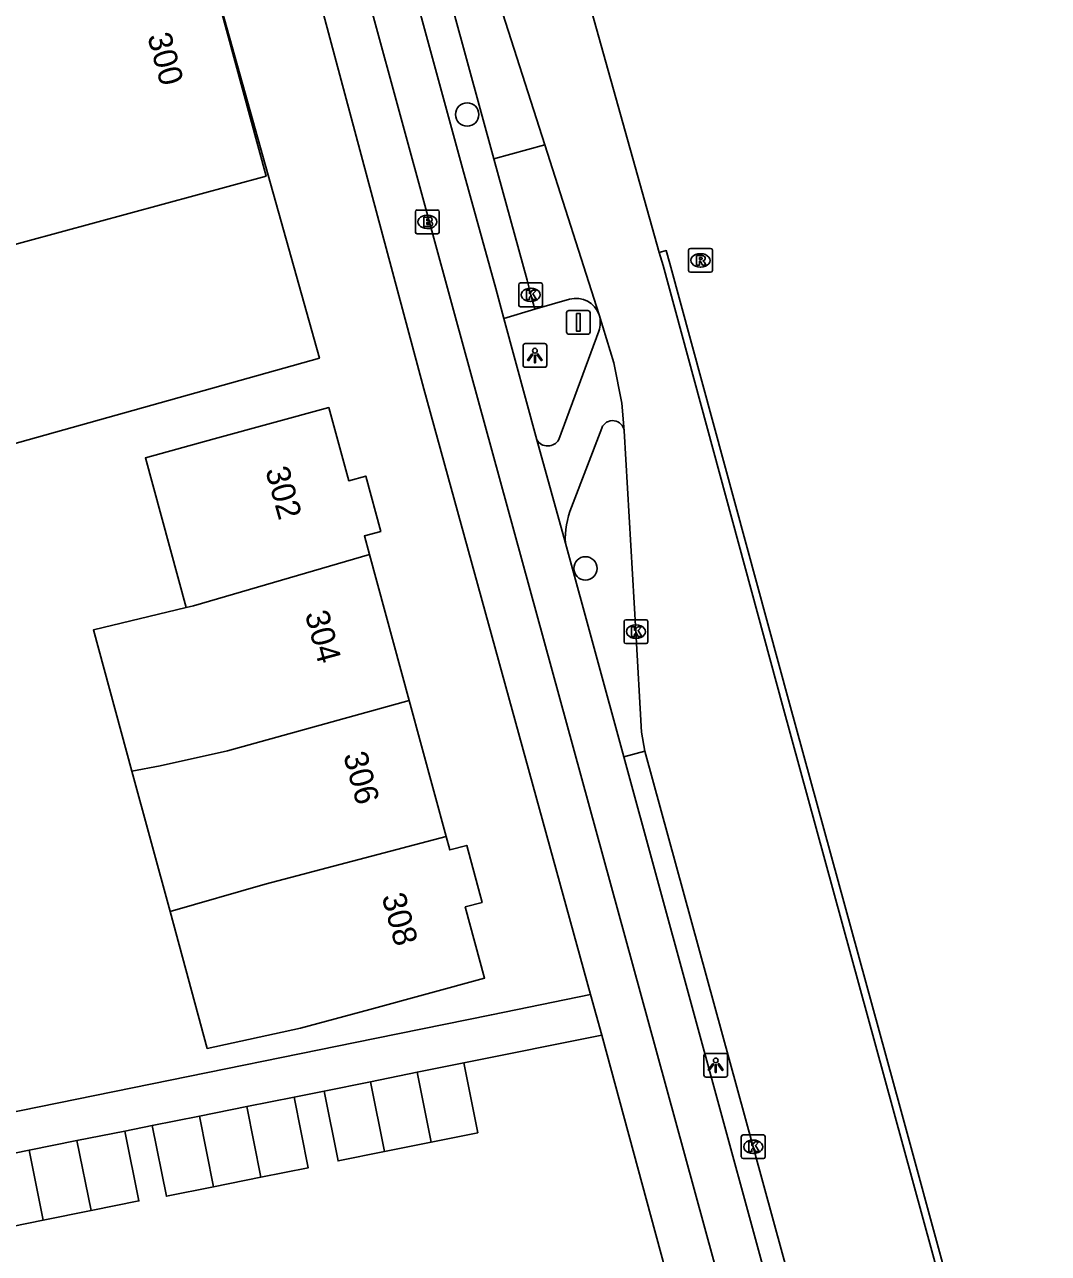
# Model space of a CAD drawing. Extents: x 162250 to 162654, y 380744 to 381605.
# Drawn here: x 162593.3 to 162636.4, y 380879.3 to 380930.9 of the extents above; entities that cross this region are included whole.
import ezdxf

# ---------------------------------------------------------------- set-up
doc = ezdxf.new("R2010")
doc.units = 0
for name, color, linetype in [('IMGEO_Boom', 7, 'Continuous'), ('IMGEO_Brandkraan', 7, 'Continuous'), ('IMGEO_Fietspad_gesloten', 7, 'Continuous'), ('IMGEO_Fietspad_open', 7, 'Continuous'), ('IMGEO_Kolk', 7, 'Continuous'), ('IMGEO_Lichtpunt', 7, 'Continuous'), ('IMGEO_Pand', 7, 'Continuous'), ('IMGEO_Pand_nummerreeks', 7, 'Continuous'), ('IMGEO_Pand_vergunning_verleend', 7, 'Continuous'), ('IMGEO_Parkeervlak_open', 7, 'Continuous'), ('IMGEO_Rijbaan_regionaal_gesloten', 7, 'Continuous'), ('IMGEO_Rioolput', 7, 'Continuous'), ('IMGEO_Verkeersbordpaal', 7, 'Continuous'), ('IMGEO_Verkeerseiland_groen', 7, 'Continuous'), ('IMGEO_Voetpad_open', 7, 'Continuous')]:
    doc.layers.add(name, color=color, linetype=linetype)

msp = doc.modelspace()

# ---------------------------------------------------------------- linework, layer by layer
at = {"layer": 'IMGEO_Boom'}
for centre in [(162611.944, 380927.149), (162616.915, 380908.077)]:
    msp.add_circle(centre, 0.489, dxfattribs=at)
at = {"layer": 'IMGEO_Brandkraan'}
for p, q in [((162609.77, 380922.21), (162609.77, 380923.062)), ((162609.845, 380923.136), (162610.697, 380923.136)), ((162610.258, 380922.916), (162610.283, 380922.916)), ((162610.771, 380923.062), (162610.771, 380922.21)), ((162610.281, 380922.356), (162610.256, 380922.356)), ((162610.697, 380922.136), (162609.845, 380922.136))]:
    msp.add_line(p, q, dxfattribs=at)
for points in [[(162609.77, 380922.21), (162609.77, 380923.062)], [(162609.845, 380923.136), (162610.697, 380923.136)], [(162610.771, 380923.062), (162610.771, 380922.21)], [(162610.118, 380922.836), (162610.118, 380922.436), (162610.331, 380922.436)], [(162610.349, 380922.836), (162610.118, 380922.836)], [(162610.297, 380922.755), (162610.243, 380922.755), (162610.243, 380922.679)], [(162610.243, 380922.679), (162610.296, 380922.679)], [(162610.305, 380922.603), (162610.243, 380922.603), (162610.243, 380922.522)], [(162610.243, 380922.522), (162610.305, 380922.522)], [(162610.697, 380922.136), (162609.845, 380922.136)]]:
    msp.add_lwpolyline(points, dxfattribs=at)
for centre, radius, start, end in [((162609.847, 380923.06), 0.0765, 91.552, 178.448), ((162609.847, 380923.06), 0.0765, 91.552, 178.448), ((162610.695, 380923.06), 0.0765, 1.552, 88.448), ((162610.695, 380923.06), 0.0765, 1.552, 88.448), ((162610.298, 380922.717), 0.0379, 267.8285, 90.9355), ((162610.306, 380922.562), 0.0404, 269.8759, 90.5077), ((162610.337, 380922.687), 0.251, 268.6676, 293.5347), ((162610.353, 380922.691), 0.145, 59.4692, 91.5367), ((162610.378, 380922.738), 0.0922, 285.5137, 58.1501), ((162610.383, 380922.546), 0.105, 301.3115, 78.989), ((162609.847, 380922.212), 0.0765, 181.552, 268.448), ((162609.847, 380922.212), 0.0765, 181.552, 268.448), ((162610.695, 380922.212), 0.0765, 271.552, 358.448), ((162610.695, 380922.212), 0.0765, 271.552, 358.448)]:
    msp.add_arc(centre, radius, start, end, dxfattribs=at)
for centre, major_axis, ratio, start_param, end_param in [((162610.257, 380922.636), (-0.387, 0.002), 0.722429, 4.712389, 7.853982), ((162610.282, 380922.636), (-0.39, 0.002), 0.717154, 1.570796, 4.712389)]:
    msp.add_ellipse(centre, major_axis=major_axis, ratio=ratio, start_param=start_param, end_param=end_param, dxfattribs=at)
at = {"layer": 'IMGEO_Fietspad_gesloten'}
for points in [[(162536.398, 381200.372), (162539.144, 381190.342), (162540.943, 381183.77), (162548.984, 381154.395), (162551.592, 381144.84), (162551.645, 381144.647), (162554.806, 381133.124), (162560.736, 381111.446), (162562.992, 381103.198), (162573.052, 381066.398), (162577.335, 381050.801), (162584.526, 381024.553), (162587.309, 381014.367), (162588.433, 381010.254), (162590.219, 381003.716), (162603.154, 380956.316), (162606.977, 380942.372), (162608.338, 380937.386), (162611.747, 380924.889), (162613.149, 380919.833), (162613.482, 380918.571)], [(162626.231, 380864.638), (162619.54, 380889.111), (162611.456, 380918.623), (162600.985, 380956.955), (162588.336, 381003.241), (162586.64, 381009.407), (162585.413, 381013.87), (162582.804, 381023.355), (162575.392, 381050.363), (162571.085, 381066.091), (162561.27, 381101.934), (162558.72, 381111.249), (162552.836, 381132.744), (162549.852, 381143.643)], [(162614.869, 380913.477), (162613.482, 380918.571)], [(162616.074, 380909.136), (162614.869, 380913.477)], [(162618.527, 380900.159), (162616.074, 380909.136)], [(162628.093, 380865.109), (162618.527, 380900.159)]]:
    msp.add_lwpolyline(points, dxfattribs=at)
at = {"layer": 'IMGEO_Fietspad_open'}
for points in [[(162615.795, 380913.486), (162617.477, 380918.04)], [(162617.598, 380913.973), (162616.334, 380910.645)]]:
    msp.add_lwpolyline(points, dxfattribs=at)
for centre, radius, start, end in [((162616.332, 380918.413), 1.204, 341.9353, 15.242), ((162618.057, 380913.795), 0.492, 6.7574, 158.799), ((162615.329, 380913.763), 0.542, 211.8287, 329.285), ((162619.429, 380909.335), 3.361, 157.0559, 183.392)]:
    msp.add_arc(centre, radius, start, end, dxfattribs=at)
at = {"layer": 'IMGEO_Kolk'}
for p, q in [((162614.113, 380919.144), (162614.113, 380919.996)), ((162614.188, 380920.07), (162615.04, 380920.07)), ((162614.601, 380919.85), (162614.626, 380919.85)), ((162615.114, 380919.996), (162615.114, 380919.144)), ((162614.624, 380919.29), (162614.599, 380919.29)), ((162615.04, 380919.07), (162614.188, 380919.07)), ((162618.535, 380904.994), (162618.535, 380905.846)), ((162618.61, 380905.92), (162619.462, 380905.92)), ((162619.536, 380905.846), (162619.536, 380904.994)), ((162619.023, 380905.7), (162619.048, 380905.7)), ((162619.462, 380904.92), (162618.61, 380904.92)), ((162619.046, 380905.14), (162619.021, 380905.14)), ((162623.464, 380883.349), (162623.464, 380884.201)), ((162623.539, 380884.275), (162624.391, 380884.275)), ((162624.465, 380884.201), (162624.465, 380883.349)), ((162623.952, 380884.055), (162623.977, 380884.055)), ((162624.391, 380883.275), (162623.539, 380883.275)), ((162623.975, 380883.495), (162623.95, 380883.495))]:
    msp.add_line(p, q, dxfattribs=at)
for points in [[(162614.113, 380919.144), (162614.113, 380919.996)], [(162614.188, 380920.07), (162615.04, 380920.07)], [(162614.434, 380919.77), (162614.557, 380919.77), (162614.557, 380919.619), (162614.687, 380919.77), (162614.851, 380919.77), (162614.705, 380919.619), (162614.858, 380919.37), (162614.706, 380919.37), (162614.621, 380919.534), (162614.557, 380919.467), (162614.557, 380919.37), (162614.434, 380919.37), (162614.434, 380919.77)], [(162615.114, 380919.996), (162615.114, 380919.144)], [(162615.04, 380919.07), (162614.188, 380919.07)], [(162618.535, 380904.994), (162618.535, 380905.846)], [(162618.61, 380905.92), (162619.462, 380905.92)], [(162619.536, 380905.846), (162619.536, 380904.994)], [(162618.856, 380905.62), (162618.979, 380905.62), (162618.979, 380905.469), (162619.109, 380905.62), (162619.273, 380905.62), (162619.127, 380905.469), (162619.28, 380905.22), (162619.128, 380905.22), (162619.043, 380905.384), (162618.979, 380905.317), (162618.979, 380905.22), (162618.856, 380905.22), (162618.856, 380905.62)], [(162619.462, 380904.92), (162618.61, 380904.92)], [(162623.464, 380883.349), (162623.464, 380884.201)], [(162623.539, 380884.275), (162624.391, 380884.275)], [(162624.465, 380884.201), (162624.465, 380883.349)], [(162623.785, 380883.975), (162623.908, 380883.975), (162623.908, 380883.824), (162624.038, 380883.975), (162624.202, 380883.975), (162624.056, 380883.824), (162624.209, 380883.575), (162624.057, 380883.575), (162623.972, 380883.739), (162623.908, 380883.672), (162623.908, 380883.575), (162623.785, 380883.575), (162623.785, 380883.975)], [(162624.391, 380883.275), (162623.539, 380883.275)]]:
    msp.add_lwpolyline(points, dxfattribs=at)
for centre, start, end in [((162614.19, 380919.994), 91.552, 178.448), ((162614.19, 380919.994), 91.552, 178.448), ((162615.038, 380919.994), 1.552, 88.448), ((162615.038, 380919.994), 1.552, 88.448), ((162614.19, 380919.146), 181.552, 268.448), ((162614.19, 380919.146), 181.552, 268.448), ((162615.038, 380919.146), 271.552, 358.448), ((162615.038, 380919.146), 271.552, 358.448), ((162618.612, 380905.844), 91.552, 178.448), ((162618.612, 380905.844), 91.552, 178.448), ((162619.46, 380905.844), 1.552, 88.448), ((162619.46, 380905.844), 1.552, 88.448), ((162618.612, 380904.996), 181.552, 268.448), ((162618.612, 380904.996), 181.552, 268.448), ((162619.46, 380904.996), 271.552, 358.448), ((162619.46, 380904.996), 271.552, 358.448), ((162623.541, 380884.199), 91.552, 178.448), ((162623.541, 380884.199), 91.552, 178.448), ((162624.389, 380884.199), 1.552, 88.448), ((162624.389, 380884.199), 1.552, 88.448), ((162623.541, 380883.351), 181.552, 268.448), ((162623.541, 380883.351), 181.552, 268.448), ((162624.389, 380883.351), 271.552, 358.448), ((162624.389, 380883.351), 271.552, 358.448)]:
    msp.add_arc(centre, 0.0765, start, end, dxfattribs=at)
for centre, major_axis, ratio, start_param, end_param in [((162614.6, 380919.57), (-0.387, 0.002), 0.722429, 4.712389, 7.853982), ((162614.625, 380919.57), (-0.39, 0.002), 0.717154, 1.570796, 4.712389), ((162619.022, 380905.42), (-0.387, 0.002), 0.722429, 4.712389, 7.853982), ((162619.047, 380905.42), (-0.39, 0.002), 0.717154, 1.570796, 4.712389), ((162623.951, 380883.775), (-0.387, 0.002), 0.722429, 4.712389, 7.853982), ((162623.976, 380883.775), (-0.39, 0.002), 0.717154, 1.570796, 4.712389)]:
    msp.add_ellipse(centre, major_axis=major_axis, ratio=ratio, start_param=start_param, end_param=end_param, dxfattribs=at)
at = {"layer": 'IMGEO_Lichtpunt'}
for p, q in [((162614.291, 380917.427), (162614.291, 380916.62)), ((162614.291, 380917.427), (162614.291, 380916.62)), ((162615.193, 380917.522), (162614.385, 380917.522)), ((162615.193, 380917.522), (162614.385, 380917.522)), ((162615.287, 380916.62), (162615.287, 380917.427)), ((162615.287, 380916.62), (162615.287, 380917.427)), ((162614.385, 380916.526), (162615.193, 380916.526)), ((162614.385, 380916.526), (162615.193, 380916.526)), ((162621.889, 380887.604), (162621.889, 380886.797)), ((162621.889, 380887.604), (162621.889, 380886.797)), ((162622.791, 380887.699), (162621.983, 380887.699)), ((162622.791, 380887.699), (162621.983, 380887.699)), ((162622.885, 380886.797), (162622.885, 380887.604)), ((162622.885, 380886.797), (162622.885, 380887.604)), ((162621.983, 380886.703), (162622.791, 380886.703)), ((162621.983, 380886.703), (162622.791, 380886.703))]:
    msp.add_line(p, q, dxfattribs=at)
for points in [[(162614.665, 380917.091), (162614.704, 380917.063), (162614.516, 380916.801), (162614.478, 380916.828), (162614.665, 380917.091)], [(162614.767, 380917.043), (162614.814, 380917.043), (162614.814, 380916.721), (162614.767, 380916.721), (162614.767, 380917.043)], [(162614.877, 380917.063), (162614.915, 380917.09), (162615.102, 380916.828), (162615.063, 380916.8), (162614.877, 380917.063)], [(162622.263, 380887.268), (162622.302, 380887.24), (162622.114, 380886.978), (162622.076, 380887.005), (162622.263, 380887.268)], [(162622.365, 380887.22), (162622.412, 380887.22), (162622.412, 380886.898), (162622.365, 380886.898), (162622.365, 380887.22)], [(162622.475, 380887.24), (162622.513, 380887.267), (162622.7, 380887.005), (162622.661, 380886.977), (162622.475, 380887.24)]]:
    msp.add_lwpolyline(points, dxfattribs=at)
for centre in [(162614.79, 380917.225), (162622.388, 380887.402)]:
    msp.add_circle(centre, 0.0994, dxfattribs=at)
for centre, start, end in [((162614.385, 380917.427), 90, 180), ((162614.385, 380917.427), 90, 180), ((162615.193, 380917.427), 0, 90), ((162615.193, 380917.427), 0, 90), ((162614.385, 380916.62), 180, 270), ((162614.385, 380916.62), 180, 270), ((162615.193, 380916.62), 270, 0), ((162615.193, 380916.62), 270, 360), ((162621.983, 380887.604), 90, 180), ((162621.983, 380887.604), 90, 180), ((162622.791, 380887.604), 0, 90), ((162622.791, 380887.604), 0, 90), ((162621.983, 380886.797), 180, 270), ((162621.983, 380886.797), 180, 270), ((162622.791, 380886.797), 270, 0), ((162622.791, 380886.797), 270, 360)]:
    msp.add_arc(centre, 0.0946, start, end, dxfattribs=at)
at = {"layer": 'IMGEO_Pand'}
for points in [[(162599.77, 380935.183), (162600.55, 380935.395), (162603.496, 380924.559), (162581.842, 380918.674), (162582.635, 380915.76), (162577.91, 380914.476)], [(162607.84, 380908.665), (162607.628, 380909.443), (162608.316, 380909.63), (162607.684, 380911.953), (162606.968, 380911.758), (162606.131, 380914.837), (162601.307, 380913.526), (162598.427, 380912.717), (162600.136, 380906.429)], [(162607.84, 380908.665), (162600.448, 380906.503), (162600.136, 380906.429)], [(162609.509, 380902.523), (162607.84, 380908.665)], [(162600.136, 380906.429), (162596.238, 380905.5), (162597.853, 380899.561)], [(162597.853, 380899.561), (162599.042, 380899.777), (162601.877, 380900.417), (162609.509, 380902.523)], [(162609.509, 380902.523), (162611.062, 380896.809)], [(162599.458, 380893.661), (162597.853, 380899.561)], [(162611.062, 380896.809), (162611.215, 380896.246), (162611.923, 380896.438), (162612.573, 380894.044), (162611.863, 380893.851), (162612.676, 380890.86), (162607.852, 380889.548), (162604.939, 380888.756), (162601.023, 380887.907), (162599.458, 380893.661)], [(162599.458, 380893.661), (162603.459, 380894.815), (162611.062, 380896.809)], [(162611.801, 380887.295), (162609.844, 380886.902)], [(162610.433, 380883.968), (162612.39, 380884.361), (162611.801, 380887.295)], [(162609.844, 380886.902), (162607.887, 380886.509)], [(162609.844, 380886.902), (162610.433, 380883.968)], [(162607.887, 380886.509), (162605.93, 380886.116)], [(162608.476, 380883.575), (162607.887, 380886.509)], [(162604.67, 380885.863), (162602.682, 380885.464)], [(162603.279, 380882.492), (162605.266, 380882.891), (162604.67, 380885.863)], [(162605.93, 380886.116), (162606.52, 380883.182), (162608.476, 380883.575)], [(162602.682, 380885.464), (162600.694, 380885.064)], [(162603.279, 380882.492), (162602.682, 380885.464)], [(162600.694, 380885.064), (162598.707, 380884.665)], [(162598.707, 380884.665), (162599.304, 380881.694), (162601.291, 380882.093)], [(162601.291, 380882.093), (162600.694, 380885.064)], [(162597.559, 380884.435), (162595.548, 380884.031)], [(162596.138, 380881.092), (162598.149, 380881.496), (162597.559, 380884.435)], [(162593.541, 380883.628), (162591.533, 380883.225)], [(162595.548, 380884.031), (162593.541, 380883.628)], [(162594.131, 380880.689), (162593.541, 380883.628)], [(162596.138, 380881.092), (162595.548, 380884.031)], [(162608.476, 380883.575), (162610.433, 380883.968)], [(162591.533, 380883.225), (162592.124, 380880.286), (162594.131, 380880.689)], [(162601.291, 380882.093), (162603.279, 380882.492)], [(162594.131, 380880.689), (162596.138, 380881.092)]]:
    msp.add_lwpolyline(points, dxfattribs=at)
at = {"layer": 'IMGEO_Pand_vergunning_verleend'}
msp.add_lwpolyline([(162586.803, 380931.515), (162593.538, 380933.518), (162599.77, 380935.183), (162600.55, 380935.395), (162605.736, 380916.916), (162591.983, 380913.056), (162586.803, 380931.515)], dxfattribs=at)
at = {"layer": 'IMGEO_Parkeervlak_open'}
for points in [[(162613.064, 380925.283), (162609.656, 380937.755), (162608.292, 380942.728), (162607.98, 380943.81), (162605.426, 380953.253), (162604.609, 380956.168), (162603.851, 380959.936), (162601.87, 380967.154), (162600.524, 380971.974), (162600.563, 380972.483), (162601.31, 380975.004)], [(162613.064, 380925.283), (162615.211, 380925.872)], [(162614.788, 380918.975), (162614.614, 380919.57), (162614.461, 380920.194), (162613.064, 380925.283)], [(162614.788, 380918.975), (162616.25, 380919.388)]]:
    msp.add_lwpolyline(points, dxfattribs=at)
msp.add_arc((162616.52, 380918.393), 1.031, 19.0988, 105.149, dxfattribs=at)
at = {"layer": 'IMGEO_Rijbaan_regionaal_gesloten'}
for points in [[(162600.546, 380991.029), (162601.527, 380987.343), (162620.018, 380921.349)], [(162601.341, 380976.353), (162605.814, 380960.337), (162605.531, 380960.193), (162607.357, 380953.618), (162613.211, 380932.13), (162615.211, 380925.872)], [(162615.211, 380925.872), (162617.494, 380918.73)], [(162620.018, 380921.349), (162620.306, 380921.431), (162620.462, 380920.882), (162625.488, 380902.406), (162630.138, 380885.423), (162635.982, 380863.999), (162636.368, 380862.563), (162636.23, 380862.519), (162636.218, 380862.515)], [(162632.323, 380876.275), (162629.849, 380885.344), (162625.199, 380902.327), (162620.173, 380920.802), (162620.018, 380921.349)], [(162617.494, 380918.73), (162618.1, 380916.717), (162618.441, 380915.019), (162618.545, 380913.853)], [(162618.545, 380913.853), (162619.036, 380905.42), (162619.269, 380901.189), (162619.411, 380900.399)], [(162619.411, 380900.399), (162623.965, 380883.775), (162626.435, 380874.703)]]:
    msp.add_lwpolyline(points, dxfattribs=at)
at = {"layer": 'IMGEO_Rioolput'}
for p, q in [((162621.247, 380920.594), (162621.247, 380921.446)), ((162621.322, 380921.52), (162622.174, 380921.52)), ((162621.735, 380921.3), (162621.76, 380921.3)), ((162622.248, 380921.446), (162622.248, 380920.594)), ((162622.174, 380920.52), (162621.322, 380920.52)), ((162621.758, 380920.74), (162621.733, 380920.74))]:
    msp.add_line(p, q, dxfattribs=at)
for points in [[(162621.247, 380920.594), (162621.247, 380921.446)], [(162621.322, 380921.52), (162622.174, 380921.52)], [(162622.248, 380921.446), (162622.248, 380920.594)], [(162621.836, 380921.218), (162621.584, 380921.22), (162621.584, 380920.82)], [(162621.584, 380920.82), (162621.708, 380920.82), (162621.708, 380920.982), (162621.719, 380920.982)], [(162621.762, 380921.139), (162621.708, 380921.139), (162621.708, 380921.058)], [(162621.708, 380921.058), (162621.76, 380921.058)], [(162621.766, 380920.953), (162621.837, 380920.82), (162621.977, 380920.82), (162621.912, 380920.946)], [(162622.174, 380920.52), (162621.322, 380920.52)]]:
    msp.add_lwpolyline(points, dxfattribs=at)
for centre, radius, start, end in [((162621.324, 380921.444), 0.0765, 91.552, 178.448), ((162621.324, 380921.444), 0.0765, 91.552, 178.448), ((162622.172, 380921.444), 0.0765, 1.552, 88.448), ((162622.172, 380921.444), 0.0765, 1.552, 88.448), ((162621.718, 380920.929), 0.0533, 26.0293, 88.6989), ((162621.744, 380921.247), 0.19, 274.7715, 282.9687), ((162621.768, 380921.043), 0.0964, 77.0061, 93.1865), ((162621.782, 380921.1), 0.0378, 276.6634, 79.6772), ((162621.835, 380921.108), 0.109, 350.3612, 89.416), ((162621.833, 380921.108), 0.112, 277.5842, 350.9817), ((162621.817, 380920.893), 0.108, 29.5134, 73.7905), ((162621.324, 380920.596), 0.0765, 181.552, 268.448), ((162621.324, 380920.596), 0.0765, 181.552, 268.448), ((162622.172, 380920.596), 0.0765, 271.552, 358.448), ((162622.172, 380920.596), 0.0765, 271.552, 358.448)]:
    msp.add_arc(centre, radius, start, end, dxfattribs=at)
for centre, major_axis, ratio, start_param, end_param in [((162621.734, 380921.02), (-0.387, 0.002), 0.722429, 4.712389, 7.853982), ((162621.759, 380921.02), (-0.39, 0.002), 0.717154, 1.570796, 4.712389)]:
    msp.add_ellipse(centre, major_axis=major_axis, ratio=ratio, start_param=start_param, end_param=end_param, dxfattribs=at)
at = {"layer": 'IMGEO_Verkeersbordpaal'}
for p, q in [((162616.12, 380918.013), (162616.12, 380918.813)), ((162616.12, 380918.813), (162616.12, 380918.013)), ((162616.22, 380918.913), (162617.01, 380918.913)), ((162617.01, 380918.913), (162616.22, 380918.913)), ((162617.11, 380918.813), (162617.11, 380918.013)), ((162617.11, 380918.013), (162617.11, 380918.813)), ((162617.01, 380917.913), (162616.22, 380917.913)), ((162616.22, 380917.913), (162617.01, 380917.913))]:
    msp.add_line(p, q, dxfattribs=at)
msp.add_lwpolyline([(162616.54, 380918.788), (162616.69, 380918.788), (162616.69, 380918.038), (162616.54, 380918.038), (162616.54, 380918.788)], dxfattribs=at)
for centre, start, end in [((162616.22, 380918.813), 90, 180), ((162616.22, 380918.813), 90, 180), ((162617.01, 380918.813), 0, 90), ((162617.01, 380918.813), 360, 90), ((162616.22, 380918.013), 180, 270), ((162616.22, 380918.013), 180, 270), ((162617.01, 380918.013), 270, 0), ((162617.01, 380918.013), 270, 0)]:
    msp.add_arc(centre, 0.1, start, end, dxfattribs=at)
at = {"layer": 'IMGEO_Verkeerseiland_groen'}
for points in [[(162613.482, 380918.571), (162614.788, 380918.975)], [(162618.527, 380900.159), (162619.411, 380900.399)]]:
    msp.add_lwpolyline(points, dxfattribs=at)
at = {"layer": 'IMGEO_Voetpad_open'}
for points in [[(162599.376, 380955.751), (162610.123, 380915.626), (162617.13, 380890.168)], [(162617.13, 380890.168), (162612.962, 380889.319), (162608.063, 380888.321), (162587.688, 380884.171), (162587.35, 380885.378)], [(162617.13, 380890.168), (162617.599, 380888.46)], [(162617.599, 380888.46), (162611.801, 380887.295)], [(162617.599, 380888.46), (162624.224, 380864.011)], [(162605.93, 380886.116), (162604.67, 380885.863)], [(162598.707, 380884.665), (162597.559, 380884.435)]]:
    msp.add_lwpolyline(points, dxfattribs=at)

# ---------------------------------------------------------------- texts
at = {"layer": 'IMGEO_Pand_nummerreeks'}
for s, rotation, p in [('300', 285.2095, (162598.497, 380930.443)), ('302', 285.4754, (162603.455, 380912.207)), ('304', 285.1946, (162605.119, 380906.168)), ('306', 285.1971, (162606.731, 380900.232)), ('308', 285.1971, (162608.344, 380894.294))]:
    msp.add_text(s, height=1, rotation=rotation, dxfattribs=at).set_placement(p)

doc.saveas('drawing.dxf')
